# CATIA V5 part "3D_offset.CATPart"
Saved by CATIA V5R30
Part number: Part1
Bounding box of the stored display mesh (mm): x -119.212 to 139.075, y -20 to 0.001, z -1.314 to 92.725
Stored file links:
  D:\PROJECTS\CATIA V56R 2020\Resources\Parts File\c17_catia_v6_6r2020_prt\3D_offset.CATPart
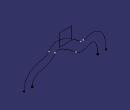
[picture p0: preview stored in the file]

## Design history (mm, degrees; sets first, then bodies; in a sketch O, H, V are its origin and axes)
Set1
  Plane1: type Offset, RefPlane zx-plane, Offset 20, reversed
  Plane2: type Offset, RefPlane Plane1, Offset 20, reversed
  Sketch1 on zx-plane, origin (0, 0, 0), H (-1, 0, 0), V (0, 0, 1)
    spline S1 through (91.2267, 2.5149) (66.4023, 45.9575) (45.4198, 38.8648) (17.3446, 45.9575)
  Sketch2 on Plane1, origin (0, -20, 0), H (-1, 0, 0), V (0, 0, 1)
    spline S1 through (-32.364, 58.2527) (-70.3912, 34.0536) (-101.7704, 22.6188) (-111.0777, -1.3144)
  Connect1: Curve1 Sketch2, Point1 vertex of Sketch2, Tension1 1, Curve2 Sketch1, Point2 vertex of Sketch1, Tension2 1
  Join1: Elements (Connect1; Sketch1; Sketch2)
  3DCurveOffset1: Curve Join1, Direction Plane2, Offset -28, CornerRadius 10, CornerTension 0.5
Body1 (main body)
